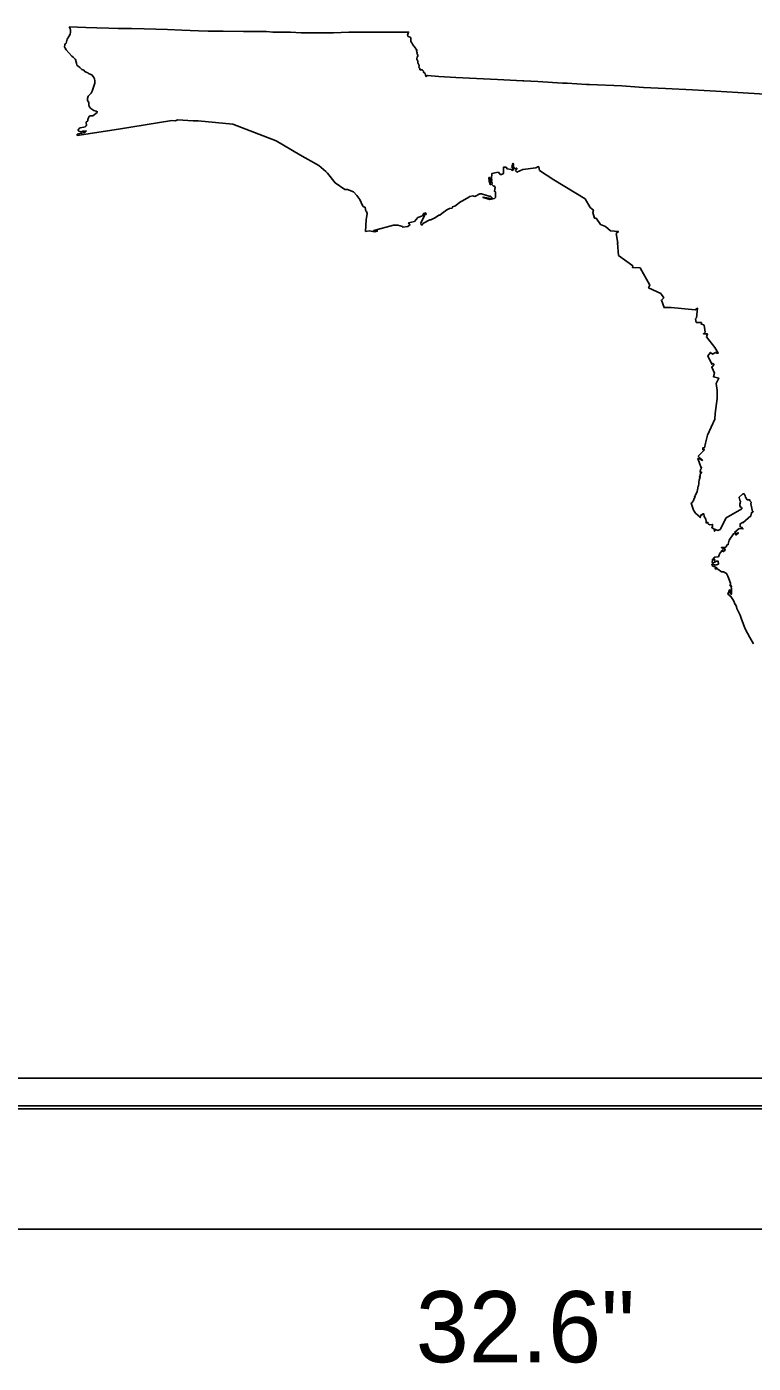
# Model space of a CAD drawing. Extents: x 0 to 770, y 0 to 495.
# Drawn here: x 378.2 to 413.9, y 22.1 to 87.9 of the extents above; entities that cross this region are included whole.
import ezdxf

# ---------------------------------------------------------------- set-up
doc = ezdxf.new("R2010")
doc.units = 0
for name, color, linetype in [('GSBWFill', 7, 'Continuous'), ('GSColorFill', 7, 'Continuous'), ('GSDims', 7, 'Continuous'), ('GSOutline', 7, 'Continuous'), ('SupstrConc', 7, 'Continuous')]:
    doc.layers.add(name, color=color, linetype=linetype)

msp = doc.modelspace()

# ---------------------------------------------------------------- linework, layer by layer
at = {"layer": 'GSBWFill'}
for p, q in [((444.968, 36.123), (363.983, 36.123)), ((363.983, 34.623), (444.968, 34.623))]:
    msp.add_line(p, q, dxfattribs=at)
at = {"layer": 'GSColorFill'}
for p, q in [((444.968, 36.123), (363.983, 36.123)), ((363.968, 34.623), (444.968, 34.623)), ((444.968, 34.773), (363.969, 34.773)), ((363.969, 34.623), (444.968, 34.623)), ((363.983, 34.623), (444.968, 34.623))]:
    msp.add_line(p, q, dxfattribs=at)
at = {"layer": 'GSDims'}
msp.add_line((370.718, 28.696), (438.218, 28.696), dxfattribs=at)
at = {"layer": 'GSOutline'}
for p, q in [((363.968, 36.123), (444.968, 36.123)), ((363.968, 34.623), (444.968, 34.623))]:
    msp.add_line(p, q, dxfattribs=at)
at = {"layer": 'SupstrConc'}
for p, q in [((382.691, 82.807), (385.317, 83.246)), ((380.662, 82.5), (382.691, 82.807)), ((410.974, 64.585), (410.882, 64.444)), ((412.218, 61.878), (412.183, 61.779))]:
    msp.add_line(p, q, dxfattribs=at)
for points in [[(380.268, 87.851), (380.31, 87.767), (380.324, 87.683), (380.324, 87.577), (380.31, 87.479), (380.247, 87.373), (380.17, 87.24), (380.113, 87.043), (380.064, 87.008), (380.05, 86.958), (380.029, 86.867), (380.064, 86.797), (380.113, 86.712), (380.395, 86.41), (380.458, 86.361), (380.556, 86.262), (380.592, 86.206), (380.592, 86.157), (380.606, 86.122), (380.606, 86.1), (380.627, 86.051), (380.641, 85.967), (380.662, 85.939), (380.711, 85.904), (380.796, 85.854), (380.824, 85.819), (380.894, 85.749), (380.943, 85.735), (380.985, 85.721), (381.035, 85.65), (381.105, 85.615), (381.189, 85.587), (381.217, 85.545), (381.302, 85.51), (381.4, 85.461), (381.471, 85.362), (381.506, 85.292), (381.52, 85.193), (381.52, 85.074), (381.4, 84.68), (381.351, 84.582), (381.288, 84.511), (381.203, 84.434), (381.168, 84.329), (381.168, 84.23), (381.238, 84.125), (381.238, 84.075), (381.238, 84.005), (381.253, 83.921), (381.337, 83.836), (381.485, 83.738), (381.59, 83.703), (381.646, 83.668), (381.646, 83.64), (381.421, 83.464), (381.351, 83.464), (381.302, 83.464), (381.253, 83.443), (381.203, 83.344), (381.189, 83.295), (381.189, 83.225), (381.105, 83.161), (381.105, 83.126), (381.119, 83.028), (381.105, 82.979), (381.049, 82.922), (380.985, 82.908), (380.81, 82.873), (380.76, 82.845), (380.711, 82.782), (380.711, 82.754), (380.746, 82.718), (380.859, 82.683), (380.943, 82.718), (381.105, 82.718), (381.07, 82.683), (381.021, 82.648), (380.88, 82.62), (380.796, 82.599), (380.662, 82.564), (380.662, 82.5)], [(402.621, 85.193), (402.571, 85.193), (401.313, 85.257), (400.286, 85.306), (399.267, 85.362), (398.437, 85.411), (397.874, 85.447), (397.79, 85.411), (397.762, 85.545), (397.678, 85.615), (397.678, 85.672), (397.628, 85.721), (397.593, 85.735), (397.509, 85.735), (397.495, 85.77), (397.495, 85.805), (397.46, 85.854), (397.474, 85.939), (397.41, 86.072), (397.41, 86.157), (397.361, 86.262), (397.375, 86.382), (397.41, 86.396), (397.41, 86.466), (397.389, 86.48), (397.361, 86.543), (397.375, 86.579), (397.34, 86.649), (397.361, 86.698), (397.235, 86.867), (397.214, 86.902), (397.15, 86.986), (397.115, 87.057), (397.052, 87.12), (397.052, 87.19), (397.066, 87.261), (397.066, 87.31), (397.031, 87.338), (396.932, 87.373), (396.897, 87.443), (396.946, 87.591), (395.814, 87.591), (394.9, 87.577), (394.007, 87.577), (393.262, 87.556), (392.355, 87.556), (391.666, 87.556), (391.153, 87.577), (390.274, 87.591), (389.971, 87.619), (388.839, 87.619), (387.841, 87.633), (387.096, 87.633), (386.624, 87.647), (385.809, 87.683), (385.099, 87.718), (383.946, 87.753), (383.334, 87.767), (382.673, 87.767), (382.216, 87.781), (381.618, 87.802), (381.084, 87.816), (380.268, 87.851)], [(404.751, 85.074), (404.519, 85.074), (403.296, 85.158), (402.621, 85.193)], [(414.722, 84.508), (414.461, 84.533), (413.139, 84.617), (412.049, 84.68), (410.903, 84.75), (409.582, 84.814), (408.499, 84.87), (407.43, 84.94), (405.841, 85.011), (405.7, 85.011), (404.751, 85.074)], [(385.317, 83.246), (385.499, 83.225), (385.584, 83.274), (386.364, 83.225), (386.603, 83.225), (388.315, 83.053)], [(388.315, 83.053), (390.442, 82.233), (391.596, 81.551), (392.538, 81.017)], [(392.538, 81.017), (392.882, 80.736), (392.967, 80.651), (393.346, 80.18), (393.81, 79.843), (393.951, 79.843), (394.239, 79.723), (394.408, 79.554)], [(400.947, 79.35), (401.165, 79.4), (401.214, 79.456), (401.214, 79.723), (401.179, 79.772), (401.165, 79.758), (401.2, 79.941), (401.179, 80.011), (401.13, 80.011), (401.046, 80.089), (401.06, 80.152), (401.032, 80.236), (400.961, 80.236), (400.961, 80.166), (400.982, 80.089), (400.961, 80.089), (400.912, 80.25), (400.898, 80.433), (400.912, 80.433), (400.982, 80.384), (400.982, 80.3), (401.01, 80.286), (401.046, 80.3), (401.032, 80.384), (401.046, 80.637), (401.278, 80.686), (401.362, 80.7), (401.453, 80.588), (401.524, 80.588), (401.622, 80.637), (401.622, 80.947), (401.742, 80.947), (401.791, 80.862), (402.009, 80.827), (402.044, 80.785), (402.1, 80.827), (402.023, 80.961)], [(402.023, 80.961), (402.079, 81.129), (402.1, 81.108), (402.1, 81.031), (402.079, 81.01), (402.164, 80.862), (402.199, 80.862), (402.248, 80.89), (402.269, 80.89), (402.248, 80.813), (402.199, 80.771), (402.269, 80.7), (402.571, 80.827), (403.211, 80.911), (403.331, 80.975), (403.345, 80.961), (403.38, 80.785), (404.097, 80.314)], [(404.097, 80.314), (405.623, 79.379), (405.869, 78.964), (406.038, 78.83), (406.003, 78.718), (406.087, 78.436), (406.164, 78.436), (406.382, 78.12), (406.635, 78.029), (406.874, 77.811), (407.261, 77.775), (407.156, 77.677)], [(394.408, 79.554), (394.556, 79.35), (394.682, 79.062), (394.717, 79.013), (394.816, 78.964), (394.851, 78.781), (394.886, 78.76), (394.914, 78.668), (394.865, 78.352), (394.824, 77.781)], [(400.103, 79.54), (400.202, 79.505), (400.455, 79.625), (400.539, 79.625), (400.961, 79.505), (400.982, 79.519), (401.06, 79.428), (400.996, 79.4), (400.603, 79.47), (400.617, 79.456), (400.947, 79.35)], [(397.987, 78.352), (398.036, 78.352), (398.17, 78.422), (398.219, 78.436), (398.437, 78.584), (398.486, 78.584), (398.585, 78.668), (398.831, 78.844), (398.964, 78.915), (399.084, 78.929), (399.112, 78.999), (399.217, 79.027), (399.506, 79.231)], [(399.506, 79.231), (399.604, 79.294), (399.906, 79.47), (399.963, 79.505), (400.103, 79.54)], [(394.824, 77.781), (395.02, 77.811), (395.294, 77.761), (395.406, 77.79), (395.406, 77.825), (395.259, 77.811), (395.238, 77.825), (396.201, 78.085), (396.419, 78.085), (396.644, 78.029), (396.665, 77.993), (396.918, 78.029), (397.017, 78.099), (396.946, 78.204), (397.235, 78.268), (397.41, 78.472), (397.628, 78.556), (397.692, 78.668), (397.79, 78.69), (397.811, 78.619), (397.713, 78.605), (397.727, 78.556), (397.544, 78.204), (397.572, 78.099), (397.628, 78.099), (397.642, 78.169), (397.987, 78.352)], [(407.156, 77.677), (407.24, 77.199), (407.212, 77.213), (407.261, 76.601), (407.971, 76.088), (407.95, 76.011), (408.33, 75.997), (408.815, 75.132), (408.745, 75.012), (409.342, 74.731), (409.49, 74.52), (409.378, 74.407), (409.511, 74.035), (409.849, 74.035), (411.037, 73.929), (411.157, 74), (411.107, 73.529)], [(411.107, 73.529), (411.058, 73.479), (411.086, 73.304), (411.339, 73.304), (411.353, 73.282), (411.325, 73.233), (411.473, 73.17), (411.522, 72.832), (411.438, 72.748), (411.635, 72.748), (411.599, 72.593), (412, 72.073), (412.169, 71.799), (412.099, 71.799), (412.035, 71.827), (411.881, 71.75), (411.796, 71.827), (411.663, 71.665), (411.853, 71.25), (411.881, 71.293), (411.965, 71.236), (411.853, 71.103), (411.986, 70.815), (411.93, 70.632), (412.204, 70.561), (412.071, 70.294), (412.12, 69.957), (412.12, 69.563)], [(412.12, 69.563), (412.014, 68.818), (412, 68.543), (411.635, 67.763), (411.543, 67.362), (411.494, 67.137), (411.41, 67.137), (411.41, 67.053), (411.494, 67.039), (411.206, 66.75), (411.192, 66.722), (411.374, 66.554), (411.389, 66.518), (411.241, 66.617), (411.171, 66.617), (411.325, 66.16)], [(411.325, 66.16), (411.339, 66.174), (411.353, 66.174), (411.339, 66.097), (411.304, 66.075), (411.276, 65.956), (411.29, 65.928), (411.304, 65.928), (411.353, 65.942), (411.353, 65.928), (411.29, 65.843), (411.29, 65.731), (411.241, 65.731), (411.276, 65.703), (411.255, 65.597), (411.241, 65.583), (411.22, 65.414), (411.22, 65.4), (411.22, 65.365), (411.206, 65.267), (411.192, 65.267), (411.171, 65.161), (411.135, 64.993), (411.058, 64.803), (411.023, 64.775), (411.002, 64.754), (411.037, 64.754), (411.023, 64.69), (410.974, 64.62), (410.974, 64.585)], [(410.882, 64.444), (410.847, 64.416), (410.953, 64.079), (411.058, 63.924), (411.276, 63.734), (411.29, 63.699), (411.304, 63.755), (411.304, 63.769), (411.325, 63.847), (411.353, 63.847)], [(413.252, 64.416), (413.273, 64.5), (413.224, 64.557), (413.203, 64.69), (413.203, 64.704), (413.371, 64.859), (413.407, 64.873)], [(413.407, 64.873), (413.421, 64.887), (413.442, 64.873), (413.491, 64.775)], [(413.491, 64.775), (413.505, 64.718), (413.589, 64.585)], [(413.589, 64.585), (413.716, 64.585), (413.73, 64.536), (413.8, 64.444), (413.779, 64.416), (413.779, 64.381)], [(411.353, 63.847), (411.389, 63.847), (411.389, 63.896)], [(411.389, 63.896), (411.459, 63.896), (411.473, 63.755)], [(412.566, 63.692), (413.336, 64.142), (413.336, 64.177), (413.308, 64.198), (413.273, 64.226), (413.224, 64.297), (413.224, 64.332), (413.224, 64.36), (413.252, 64.416)], [(413.779, 64.381), (413.849, 64.008), (413.885, 64.008), (413.885, 63.994), (413.8, 63.945), (413.779, 63.79), (413.646, 63.671), (413.385, 63.453), (413.371, 63.467), (413.252, 63.404), (413.252, 63.249), (413.308, 63.235), (413.385, 63.15), (413.203, 63.164), (412.985, 62.989), (413.055, 62.925), (413.153, 62.961), (413.153, 62.939), (413.055, 62.855)], [(411.473, 63.755), (411.557, 63.622), (411.578, 63.516), (411.578, 63.467), (411.599, 63.432), (411.649, 63.467), (411.663, 63.467), (411.649, 63.432), (411.698, 63.382), (411.768, 63.347), (411.881, 63.368), (411.881, 63.27), (411.853, 63.214), (411.916, 63.164), (411.965, 63.15), (411.965, 63.115), (411.986, 63.045), (412, 63.045), (412, 63.115), (412.035, 63.115), (412.148, 63.073), (412.26, 63.115), (412.566, 63.692)], [(413.055, 62.855), (413.034, 62.855), (412.971, 62.925), (412.914, 62.904), (412.71, 62.588), (412.661, 62.398), (412.675, 62.398), (412.612, 62.363), (412.542, 62.25), (412.457, 62.229), (412.394, 62.229), (412.324, 62.229), (412.345, 62.215), (412.394, 62.194), (412.443, 62.194), (412.429, 62.166), (412.443, 62.145), (412.492, 62.18), (412.514, 62.11), (412.429, 62.032), (412.373, 62.061), (412.394, 62.096), (412.373, 62.11), (412.26, 61.976), (412.218, 61.878)], [(412.183, 61.779), (412, 61.758), (411.93, 61.702), (412, 61.604), (411.986, 61.589), (411.93, 61.639), (411.916, 61.667), (411.902, 61.667), (411.881, 61.653), (411.881, 61.604), (411.867, 61.519), (411.881, 61.484), (412, 61.505), (412.071, 61.554), (412.169, 61.554), (412.183, 61.421), (412.014, 61.372), (411.881, 61.435), (411.853, 61.4), (411.881, 61.336), (412.099, 61.238), (412.085, 61.203), (412.014, 61.238), (412.035, 61.182), (412.148, 61.168), (412.324, 61.041), (412.429, 61.041)], [(412.429, 61.041), (412.577, 60.957), (412.647, 60.823), (412.781, 60.472), (412.781, 60.408), (412.746, 60.366), (412.781, 60.331), (412.781, 60.366), (412.809, 60.352), (412.83, 60.317), (412.809, 60.232), (412.83, 60.232), (412.83, 59.944), (412.795, 59.944), (412.746, 60.05), (412.76, 60.099), (412.781, 60.099), (412.795, 60.134), (412.724, 60.148), (412.696, 60.05), (412.647, 59.944), (412.795, 59.832), (412.928, 59.621), (413.006, 59.438)], [(413.006, 59.438), (413.02, 59.424), (413.069, 59.318), (413.09, 59.234), (413.252, 58.911), (413.308, 58.707), (413.491, 58.236), (413.73, 57.8), (413.899, 57.49)]]:
    msp.add_lwpolyline(points, dxfattribs=at)

# ---------------------------------------------------------------- texts
at = {"layer": 'GSDims'}
msp.add_text('32.6"', height=3.5, dxfattribs=at).set_placement((397.304, 22.156))

doc.saveas('drawing.dxf')
